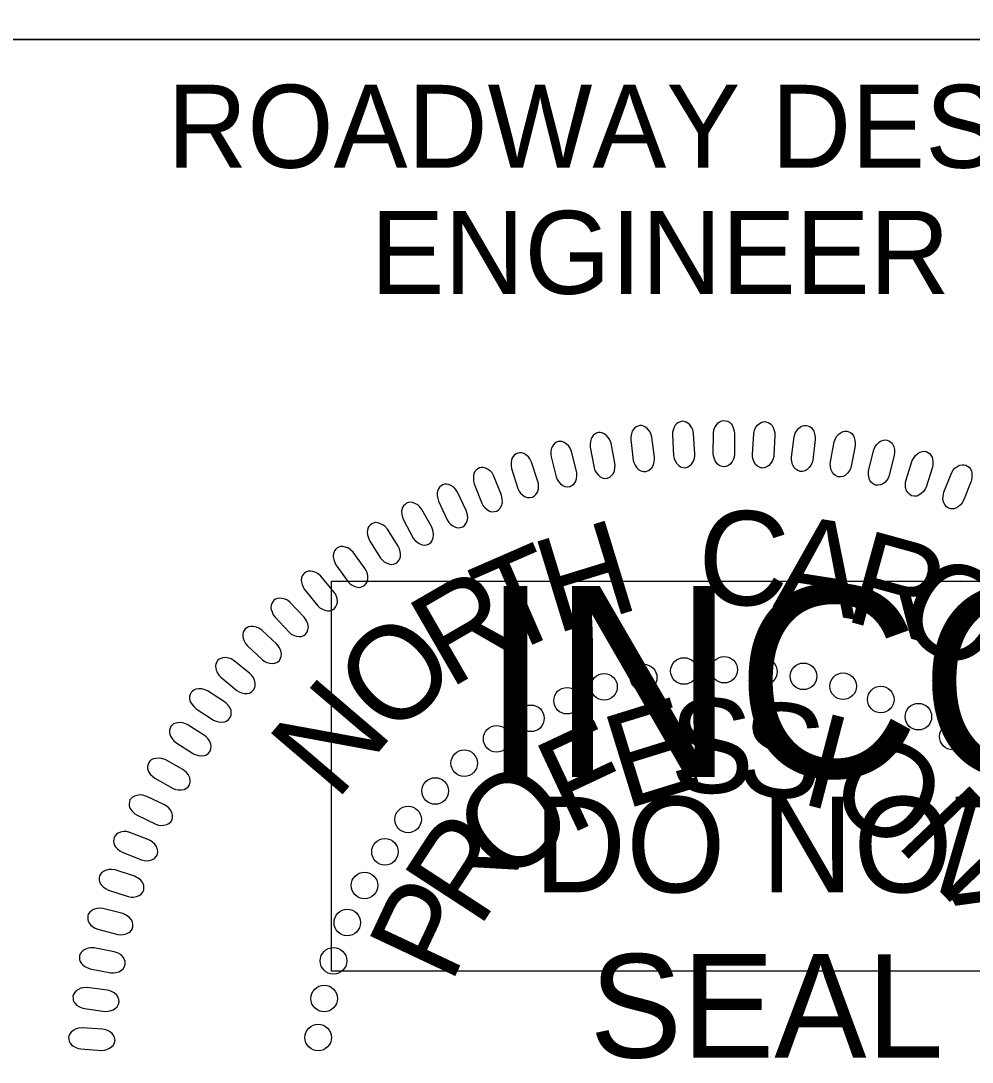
# Model space of a CAD drawing. Extents: x 497599 to 513368, y 404140 to 482942.
# Drawn here: x 507166.5 to 507223.8, y 439749.5 to 439812.2 of the extents above; entities that cross this region are included whole.
import ezdxf

# ---------------------------------------------------------------- set-up
doc = ezdxf.new("R2010")
doc.units = 0
for name, color, linetype in [('Sheet PE Seal Cell', 7, 'Continuous'), ('Sheet Profile CELL', 7, 'Continuous'), ('Sheet Sticker Incomplete CELL', 7, 'Continuous')]:
    doc.layers.add(name, color=color, linetype=linetype)

msp = doc.modelspace()

# ---------------------------------------------------------------- linework, layer by layer
at = {"layer": 'Sheet PE Seal Cell'}
for points in [[(507204.659, 439785.912), (507204.505, 439787.129), (507204.441, 439787.343), (507204.372, 439787.474), (507204.239, 439787.629), (507204.129, 439787.725), (507204.008, 439787.79), (507203.899, 439787.817), (507203.785, 439787.823), (507203.676, 439787.789), (507203.562, 439787.744), (507203.465, 439787.672), (507203.374, 439787.56), (507203.325, 439787.473), (507203.276, 439787.316), (507203.239, 439787.131), (507203.237, 439786.97), (507203.387, 439785.722), (507203.43, 439785.557), (507203.492, 439785.424), (507203.601, 439785.277), (507203.73, 439785.152), (507203.836, 439785.085), (507203.999, 439785.045), (507204.15, 439785.044), (507204.294, 439785.102), (507204.391, 439785.165), (507204.505, 439785.28), (507204.602, 439785.463), (507204.646, 439785.649), (507204.66, 439785.782)], [(507207.097, 439786.115), (507207.02, 439787.339), (507206.969, 439787.556), (507206.909, 439787.692), (507206.786, 439787.855), (507206.682, 439787.958), (507206.565, 439788.03), (507206.459, 439788.064), (507206.345, 439788.076), (507206.235, 439788.049), (507206.117, 439788.012), (507206.016, 439787.946), (507205.918, 439787.84), (507205.864, 439787.757), (507205.805, 439787.603), (507205.757, 439787.42), (507205.745, 439787.26), (507205.816, 439786.005), (507205.849, 439785.837), (507205.902, 439785.701), (507206.001, 439785.547), (507206.123, 439785.415), (507206.224, 439785.341), (507206.385, 439785.291), (507206.535, 439785.28), (507206.682, 439785.33), (507206.783, 439785.386), (507206.904, 439785.494), (507207.013, 439785.67), (507207.068, 439785.854), (507207.091, 439785.985)], [(507208.212, 439786.124), (507208.213, 439787.351), (507208.25, 439787.57), (507208.303, 439787.71), (507208.415, 439787.879), (507208.512, 439787.989), (507208.624, 439788.069), (507208.729, 439788.109), (507208.841, 439788.129), (507208.953, 439788.108), (507209.073, 439788.079), (507209.177, 439788.019), (507209.282, 439787.919), (507209.342, 439787.839), (507209.409, 439787.689), (507209.469, 439787.51), (507209.491, 439787.35), (507209.498, 439786.094), (507209.476, 439785.924), (507209.431, 439785.785), (507209.341, 439785.625), (507209.229, 439785.485), (507209.132, 439785.406), (507208.974, 439785.346), (507208.825, 439785.326), (507208.676, 439785.366), (507208.571, 439785.416), (507208.444, 439785.515), (507208.324, 439785.685), (507208.257, 439785.865), (507208.227, 439785.995)], [(507210.572, 439786.097), (507210.649, 439787.322), (507210.7, 439787.539), (507210.761, 439787.674), (507210.884, 439787.837), (507210.987, 439787.94), (507211.105, 439788.013), (507211.212, 439788.045), (507211.325, 439788.058), (507211.435, 439788.031), (507211.553, 439787.994), (507211.654, 439787.928), (507211.752, 439787.822), (507211.806, 439787.738), (507211.864, 439787.585), (507211.912, 439787.402), (507211.925, 439787.242), (507211.853, 439785.986), (507211.82, 439785.819), (507211.766, 439785.682), (507211.666, 439785.529), (507211.546, 439785.397), (507211.444, 439785.323), (507211.283, 439785.273), (507211.133, 439785.262), (507210.986, 439785.312), (507210.885, 439785.369), (507210.764, 439785.476), (507210.656, 439785.652), (507210.6, 439785.836), (507210.578, 439785.968)], [(507212.934, 439785.923), (507213.088, 439787.139), (507213.153, 439787.353), (507213.222, 439787.484), (507213.355, 439787.638), (507213.465, 439787.735), (507213.587, 439787.8), (507213.695, 439787.827), (507213.809, 439787.832), (507213.918, 439787.798), (507214.032, 439787.754), (507214.129, 439787.681), (507214.22, 439787.569), (507214.269, 439787.482), (507214.318, 439787.325), (507214.354, 439787.14), (507214.356, 439786.979), (507214.206, 439785.731), (507214.162, 439785.566), (507214.1, 439785.433), (507213.991, 439785.286), (507213.862, 439785.162), (507213.756, 439785.095), (507213.593, 439785.055), (507213.442, 439785.054), (507213.298, 439785.112), (507213.201, 439785.175), (507213.087, 439785.29), (507212.99, 439785.473), (507212.946, 439785.66), (507212.933, 439785.792)], [(507202.278, 439785.545), (507202.048, 439786.749), (507201.97, 439786.958), (507201.893, 439787.085), (507201.751, 439787.231), (507201.635, 439787.32), (507201.51, 439787.378), (507201.4, 439787.397), (507201.286, 439787.396), (507201.179, 439787.356), (507201.068, 439787.304), (507200.976, 439787.226), (507200.891, 439787.108), (507200.848, 439787.018), (507200.81, 439786.858), (507200.785, 439786.671), (507200.792, 439786.51), (507201.02, 439785.275), (507201.074, 439785.112), (507201.144, 439784.983), (507201.262, 439784.843), (507201.399, 439784.727), (507201.509, 439784.667), (507201.674, 439784.638), (507201.825, 439784.646), (507201.964, 439784.713), (507202.058, 439784.782), (507202.164, 439784.903), (507202.25, 439785.092), (507202.282, 439785.281), (507202.287, 439785.414)], [(507215.273, 439785.636), (507215.504, 439786.841), (507215.582, 439787.049), (507215.659, 439787.176), (507215.801, 439787.322), (507215.917, 439787.411), (507216.042, 439787.469), (507216.152, 439787.488), (507216.267, 439787.487), (507216.373, 439787.446), (507216.485, 439787.394), (507216.576, 439787.316), (507216.66, 439787.198), (507216.704, 439787.109), (507216.742, 439786.949), (507216.767, 439786.762), (507216.759, 439786.6), (507216.531, 439785.365), (507216.476, 439785.203), (507216.406, 439785.074), (507216.288, 439784.934), (507216.152, 439784.818), (507216.042, 439784.758), (507215.876, 439784.729), (507215.726, 439784.737), (507215.586, 439784.804), (507215.493, 439784.873), (507215.387, 439784.995), (507215.301, 439785.184), (507215.269, 439785.373), (507215.264, 439785.506)], [(507217.579, 439785.162), (507217.884, 439786.35), (507217.975, 439786.553), (507218.06, 439786.676), (507218.211, 439786.812), (507218.332, 439786.894), (507218.461, 439786.943), (507218.572, 439786.956), (507218.686, 439786.948), (507218.789, 439786.9), (507218.898, 439786.841), (507218.984, 439786.758), (507219.06, 439786.635), (507219.099, 439786.543), (507219.127, 439786.381), (507219.14, 439786.192), (507219.123, 439786.032), (507218.816, 439784.813), (507218.752, 439784.655), (507218.674, 439784.531), (507218.547, 439784.398), (507218.404, 439784.291), (507218.29, 439784.238), (507218.123, 439784.219), (507217.974, 439784.237), (507217.839, 439784.313), (507217.75, 439784.387), (507217.652, 439784.515), (507217.578, 439784.709), (507217.558, 439784.9), (507217.561, 439785.033)], [(507199.972, 439785.072), (507199.668, 439786.26), (507199.577, 439786.463), (507199.492, 439786.586), (507199.341, 439786.722), (507199.219, 439786.804), (507199.091, 439786.854), (507198.979, 439786.867), (507198.866, 439786.858), (507198.762, 439786.811), (507198.654, 439786.752), (507198.568, 439786.668), (507198.491, 439786.546), (507198.453, 439786.454), (507198.425, 439786.292), (507198.412, 439786.103), (507198.429, 439785.943), (507198.734, 439784.724), (507198.798, 439784.565), (507198.876, 439784.441), (507199.003, 439784.309), (507199.146, 439784.201), (507199.26, 439784.149), (507199.427, 439784.129), (507199.577, 439784.147), (507199.712, 439784.223), (507199.801, 439784.297), (507199.899, 439784.426), (507199.972, 439784.619), (507199.993, 439784.81), (507199.99, 439784.943)], [(507219.828, 439784.54), (507220.208, 439785.707), (507220.312, 439785.904), (507220.404, 439786.02), (507220.564, 439786.147), (507220.69, 439786.221), (507220.821, 439786.263), (507220.933, 439786.268), (507221.046, 439786.252), (507221.146, 439786.199), (507221.251, 439786.133), (507221.332, 439786.044), (507221.4, 439785.917), (507221.432, 439785.822), (507221.45, 439785.659), (507221.452, 439785.47), (507221.424, 439785.311), (507221.042, 439784.114), (507220.969, 439783.959), (507220.882, 439783.841), (507220.748, 439783.716), (507220.598, 439783.619), (507220.481, 439783.573), (507220.313, 439783.564), (507220.164, 439783.592), (507220.035, 439783.676), (507219.951, 439783.756), (507219.861, 439783.89), (507219.8, 439784.088), (507219.791, 439784.28), (507219.803, 439784.412)], [(507197.639, 439784.452), (507197.26, 439785.618), (507197.157, 439785.815), (507197.064, 439785.932), (507196.905, 439786.059), (507196.779, 439786.133), (507196.648, 439786.174), (507196.535, 439786.18), (507196.423, 439786.165), (507196.322, 439786.111), (507196.218, 439786.046), (507196.137, 439785.957), (507196.068, 439785.829), (507196.036, 439785.735), (507196.018, 439785.572), (507196.016, 439785.383), (507196.044, 439785.223), (507196.425, 439784.026), (507196.499, 439783.872), (507196.585, 439783.753), (507196.719, 439783.629), (507196.869, 439783.531), (507196.986, 439783.485), (507197.154, 439783.476), (507197.302, 439783.504), (507197.432, 439783.588), (507197.516, 439783.668), (507197.606, 439783.801), (507197.668, 439784), (507197.676, 439784.191), (507197.665, 439784.324)], [(507195.438, 439783.635), (507194.987, 439784.776), (507194.871, 439784.966), (507194.772, 439785.077), (507194.605, 439785.193), (507194.474, 439785.26), (507194.34, 439785.292), (507194.228, 439785.291), (507194.117, 439785.268), (507194.02, 439785.208), (507193.919, 439785.137), (507193.844, 439785.043), (507193.783, 439784.911), (507193.758, 439784.815), (507193.75, 439784.651), (507193.76, 439784.462), (507193.798, 439784.306), (507194.253, 439783.134), (507194.336, 439782.985), (507194.43, 439782.872), (507194.572, 439782.756), (507194.727, 439782.668), (507194.847, 439782.629), (507195.015, 439782.631), (507195.162, 439782.668), (507195.285, 439782.76), (507195.364, 439782.845), (507195.446, 439782.984), (507195.496, 439783.186), (507195.491, 439783.378), (507195.472, 439783.509)], [(507222.112, 439783.805), (507222.564, 439784.945), (507222.68, 439785.136), (507222.779, 439785.247), (507222.946, 439785.363), (507223.077, 439785.429), (507223.211, 439785.462), (507223.323, 439785.46), (507223.434, 439785.438), (507223.531, 439785.378), (507223.631, 439785.306), (507223.706, 439785.211), (507223.767, 439785.08), (507223.793, 439784.984), (507223.801, 439784.82), (507223.791, 439784.631), (507223.752, 439784.475), (507223.296, 439783.304), (507223.212, 439783.155), (507223.12, 439783.041), (507222.978, 439782.926), (507222.822, 439782.837), (507222.702, 439782.799), (507222.534, 439782.802), (507222.388, 439782.838), (507222.264, 439782.93), (507222.184, 439783.015), (507222.103, 439783.154), (507222.055, 439783.356), (507222.058, 439783.548), (507222.078, 439783.679)], [(507193.32, 439782.702), (507192.799, 439783.813), (507192.671, 439783.995), (507192.564, 439784.099), (507192.391, 439784.206), (507192.256, 439784.263), (507192.121, 439784.287), (507192.009, 439784.279), (507191.899, 439784.249), (507191.806, 439784.184), (507191.711, 439784.106), (507191.642, 439784.007), (507191.589, 439783.872), (507191.569, 439783.775), (507191.572, 439783.611), (507191.594, 439783.422), (507191.642, 439783.269), (507192.17, 439782.129), (507192.262, 439781.984), (507192.362, 439781.877), (507192.511, 439781.771), (507192.672, 439781.692), (507192.794, 439781.662), (507192.962, 439781.674), (507193.105, 439781.72), (507193.224, 439781.82), (507193.297, 439781.909), (507193.37, 439782.053), (507193.406, 439782.257), (507193.39, 439782.449), (507193.362, 439782.579)], [(507191.237, 439781.688), (507190.646, 439782.764), (507190.508, 439782.938), (507190.396, 439783.035), (507190.216, 439783.13), (507190.078, 439783.179), (507189.941, 439783.195), (507189.83, 439783.18), (507189.722, 439783.143), (507189.634, 439783.072), (507189.543, 439782.988), (507189.48, 439782.885), (507189.436, 439782.747), (507189.422, 439782.649), (507189.435, 439782.485), (507189.469, 439782.299), (507189.526, 439782.148), (507190.125, 439781.043), (507190.226, 439780.906), (507190.333, 439780.805), (507190.488, 439780.708), (507190.654, 439780.64), (507190.777, 439780.617), (507190.944, 439780.639), (507191.084, 439780.694), (507191.196, 439780.801), (507191.264, 439780.895), (507191.327, 439781.044), (507191.35, 439781.25), (507191.323, 439781.44), (507191.287, 439781.568)], [(507189.22, 439780.546), (507188.563, 439781.582), (507188.414, 439781.748), (507188.295, 439781.837), (507188.11, 439781.921), (507187.969, 439781.961), (507187.832, 439781.969), (507187.722, 439781.946), (507187.616, 439781.903), (507187.532, 439781.826), (507187.447, 439781.737), (507187.391, 439781.631), (507187.356, 439781.49), (507187.348, 439781.391), (507187.371, 439781.228), (507187.418, 439781.045), (507187.483, 439780.897), (507188.15, 439779.832), (507188.26, 439779.701), (507188.373, 439779.607), (507188.534, 439779.521), (507188.703, 439779.463), (507188.828, 439779.447), (507188.993, 439779.481), (507189.13, 439779.544), (507189.235, 439779.658), (507189.296, 439779.757), (507189.351, 439779.908), (507189.36, 439780.116), (507189.321, 439780.304), (507189.277, 439780.429)], [(507187.22, 439779.192), (507186.498, 439780.184), (507186.339, 439780.34), (507186.215, 439780.423), (507186.025, 439780.494), (507185.882, 439780.525), (507185.744, 439780.524), (507185.636, 439780.495), (507185.534, 439780.445), (507185.455, 439780.363), (507185.375, 439780.269), (507185.326, 439780.159), (507185.3, 439780.016), (507185.298, 439779.917), (507185.332, 439779.756), (507185.388, 439779.576), (507185.464, 439779.434), (507186.196, 439778.412), (507186.315, 439778.288), (507186.433, 439778.201), (507186.599, 439778.125), (507186.771, 439778.078), (507186.897, 439778.07), (507187.059, 439778.114), (507187.192, 439778.186), (507187.29, 439778.306), (507187.345, 439778.408), (507187.389, 439778.563), (507187.386, 439778.771), (507187.335, 439778.956), (507187.283, 439779.078)], [(507185.339, 439777.803), (507184.557, 439778.748), (507184.389, 439778.893), (507184.259, 439778.968), (507184.065, 439779.027), (507183.921, 439779.05), (507183.783, 439779.04), (507183.677, 439779.003), (507183.578, 439778.947), (507183.504, 439778.86), (507183.431, 439778.761), (507183.388, 439778.649), (507183.371, 439778.505), (507183.376, 439778.406), (507183.42, 439778.247), (507183.487, 439778.071), (507183.572, 439777.933), (507184.367, 439776.96), (507184.492, 439776.844), (507184.616, 439776.765), (507184.786, 439776.699), (507184.962, 439776.663), (507185.088, 439776.663), (507185.247, 439776.717), (507185.375, 439776.798), (507185.464, 439776.924), (507185.513, 439777.028), (507185.548, 439777.186), (507185.532, 439777.393), (507185.469, 439777.574), (507185.41, 439777.693)], [(507183.551, 439776.264), (507182.712, 439777.158), (507182.535, 439777.293), (507182.4, 439777.359), (507182.203, 439777.406), (507182.057, 439777.419), (507181.921, 439777.401), (507181.817, 439777.358), (507181.722, 439777.296), (507181.654, 439777.205), (507181.587, 439777.101), (507181.551, 439776.986), (507181.543, 439776.841), (507181.554, 439776.742), (507181.608, 439776.587), (507181.687, 439776.416), (507181.779, 439776.284), (507182.634, 439775.362), (507182.766, 439775.254), (507182.895, 439775.183), (507183.069, 439775.128), (507183.247, 439775.103), (507183.372, 439775.111), (507183.528, 439775.175), (507183.65, 439775.263), (507183.732, 439775.394), (507183.774, 439775.502), (507183.799, 439775.662), (507183.77, 439775.867), (507183.696, 439776.044), (507183.629, 439776.159)], [(507181.889, 439774.655), (507180.995, 439775.494), (507180.809, 439775.617), (507180.672, 439775.675), (507180.471, 439775.71), (507180.325, 439775.714), (507180.19, 439775.687), (507180.09, 439775.638), (507179.998, 439775.57), (507179.936, 439775.475), (507179.876, 439775.367), (507179.848, 439775.25), (507179.848, 439775.105), (507179.866, 439775.007), (507179.928, 439774.855), (507180.019, 439774.689), (507180.119, 439774.563), (507181.03, 439773.697), (507181.169, 439773.597), (507181.301, 439773.534), (507181.479, 439773.491), (507181.658, 439773.477), (507181.782, 439773.492), (507181.934, 439773.566), (507182.05, 439773.661), (507182.123, 439773.798), (507182.159, 439773.908), (507182.174, 439774.069), (507182.132, 439774.273), (507182.047, 439774.444), (507181.973, 439774.554)], [(507180.275, 439772.868), (507179.331, 439773.65), (507179.138, 439773.761), (507178.997, 439773.81), (507178.795, 439773.832), (507178.648, 439773.827), (507178.516, 439773.791), (507178.418, 439773.736), (507178.331, 439773.662), (507178.275, 439773.563), (507178.222, 439773.452), (507178.201, 439773.333), (507178.211, 439773.189), (507178.234, 439773.092), (507178.307, 439772.945), (507178.407, 439772.784), (507178.515, 439772.665), (507179.479, 439771.858), (507179.624, 439771.767), (507179.76, 439771.713), (507179.94, 439771.68), (507180.119, 439771.678), (507180.242, 439771.702), (507180.389, 439771.785), (507180.499, 439771.887), (507180.564, 439772.027), (507180.592, 439772.14), (507180.597, 439772.301), (507180.542, 439772.501), (507180.447, 439772.668), (507180.366, 439772.773)], [(507178.751, 439771.165), (507177.721, 439771.831), (507177.516, 439771.919), (507177.371, 439771.951), (507177.167, 439771.949), (507177.022, 439771.927), (507176.895, 439771.876), (507176.805, 439771.809), (507176.727, 439771.726), (507176.682, 439771.621), (507176.643, 439771.504), (507176.636, 439771.384), (507176.663, 439771.242), (507176.698, 439771.148), (507176.787, 439771.011), (507176.905, 439770.863), (507177.027, 439770.757), (507178.078, 439770.069), (507178.233, 439769.996), (507178.374, 439769.958), (507178.557, 439769.947), (507178.735, 439769.965), (507178.855, 439770.004), (507178.991, 439770.103), (507179.088, 439770.217), (507179.136, 439770.365), (507179.151, 439770.48), (507179.136, 439770.641), (507179.059, 439770.833), (507178.945, 439770.987), (507178.852, 439771.082)], [(507177.537, 439769.143), (507176.501, 439769.8), (507176.296, 439769.886), (507176.15, 439769.917), (507175.946, 439769.914), (507175.802, 439769.89), (507175.675, 439769.839), (507175.585, 439769.771), (507175.508, 439769.687), (507175.465, 439769.582), (507175.426, 439769.465), (507175.42, 439769.344), (507175.448, 439769.203), (507175.483, 439769.109), (507175.574, 439768.972), (507175.693, 439768.826), (507175.816, 439768.721), (507176.873, 439768.041), (507177.028, 439767.969), (507177.17, 439767.932), (507177.352, 439767.923), (507177.53, 439767.942), (507177.65, 439767.981), (507177.785, 439768.082), (507177.881, 439768.198), (507177.928, 439768.345), (507177.942, 439768.46), (507177.926, 439768.621), (507177.847, 439768.812), (507177.732, 439768.966), (507177.638, 439769.061)], [(507176.233, 439767.093), (507175.158, 439767.685), (507174.948, 439767.758), (507174.8, 439767.78), (507174.598, 439767.763), (507174.455, 439767.73), (507174.331, 439767.671), (507174.246, 439767.598), (507174.174, 439767.51), (507174.138, 439767.402), (507174.106, 439767.283), (507174.108, 439767.162), (507174.145, 439767.023), (507174.186, 439766.932), (507174.285, 439766.8), (507174.413, 439766.662), (507174.542, 439766.565), (507175.639, 439765.953), (507175.799, 439765.89), (507175.943, 439765.863), (507176.126, 439765.864), (507176.302, 439765.895), (507176.419, 439765.942), (507176.547, 439766.051), (507176.636, 439766.172), (507176.673, 439766.322), (507176.681, 439766.437), (507176.654, 439766.598), (507176.563, 439766.783), (507176.439, 439766.929), (507176.339, 439767.018)], [(507175.124, 439764.969), (507174.014, 439765.492), (507173.8, 439765.552), (507173.651, 439765.565), (507173.45, 439765.535), (507173.309, 439765.494), (507173.19, 439765.426), (507173.109, 439765.349), (507173.043, 439765.256), (507173.013, 439765.146), (507172.99, 439765.024), (507172.999, 439764.905), (507173.045, 439764.768), (507173.092, 439764.68), (507173.198, 439764.555), (507173.335, 439764.424), (507173.47, 439764.335), (507174.604, 439763.793), (507174.767, 439763.742), (507174.912, 439763.723), (507175.094, 439763.736), (507175.269, 439763.778), (507175.382, 439763.832), (507175.504, 439763.948), (507175.585, 439764.075), (507175.612, 439764.227), (507175.612, 439764.344), (507175.576, 439764.501), (507175.474, 439764.681), (507175.34, 439764.818), (507175.235, 439764.901)], [(507174.185, 439762.851), (507173.045, 439763.303), (507172.827, 439763.348), (507172.678, 439763.352), (507172.479, 439763.31), (507172.341, 439763.26), (507172.226, 439763.185), (507172.15, 439763.102), (507172.09, 439763.005), (507172.068, 439762.894), (507172.051, 439762.771), (507172.068, 439762.653), (507172.122, 439762.519), (507172.174, 439762.433), (507172.289, 439762.316), (507172.434, 439762.194), (507172.574, 439762.114), (507173.739, 439761.644), (507173.905, 439761.603), (507174.051, 439761.593), (507174.232, 439761.618), (507174.404, 439761.671), (507174.514, 439761.732), (507174.628, 439761.855), (507174.701, 439761.987), (507174.719, 439762.14), (507174.711, 439762.256), (507174.665, 439762.411), (507174.552, 439762.584), (507174.409, 439762.713), (507174.299, 439762.789)], [(507173.309, 439760.662), (507172.143, 439761.041), (507171.922, 439761.073), (507171.773, 439761.067), (507171.577, 439761.013), (507171.443, 439760.954), (507171.332, 439760.872), (507171.263, 439760.785), (507171.209, 439760.684), (507171.193, 439760.572), (507171.184, 439760.449), (507171.209, 439760.331), (507171.271, 439760.2), (507171.329, 439760.119), (507171.45, 439760.008), (507171.602, 439759.896), (507171.747, 439759.825), (507172.94, 439759.429), (507173.108, 439759.399), (507173.255, 439759.398), (507173.434, 439759.434), (507173.601, 439759.498), (507173.708, 439759.565), (507173.813, 439759.695), (507173.878, 439759.832), (507173.886, 439759.987), (507173.871, 439760.101), (507173.816, 439760.253), (507173.692, 439760.419), (507173.542, 439760.539), (507173.428, 439760.607)], [(507172.605, 439758.406), (507171.416, 439758.711), (507171.195, 439758.73), (507171.046, 439758.714), (507170.854, 439758.648), (507170.724, 439758.581), (507170.618, 439758.492), (507170.554, 439758.401), (507170.507, 439758.297), (507170.498, 439758.184), (507170.497, 439758.06), (507170.529, 439757.944), (507170.6, 439757.818), (507170.662, 439757.74), (507170.791, 439757.637), (507170.949, 439757.535), (507171.098, 439757.473), (507172.313, 439757.153), (507172.483, 439757.133), (507172.63, 439757.141), (507172.806, 439757.189), (507172.969, 439757.262), (507173.071, 439757.337), (507173.168, 439757.474), (507173.225, 439757.614), (507173.223, 439757.768), (507173.201, 439757.882), (507173.136, 439758.03), (507173.002, 439758.188), (507172.845, 439758.298), (507172.726, 439758.359)], [(507172.094, 439756.11), (507170.889, 439756.34), (507170.666, 439756.345), (507170.519, 439756.32), (507170.331, 439756.242), (507170.205, 439756.167), (507170.106, 439756.071), (507170.047, 439755.976), (507170.006, 439755.87), (507170.006, 439755.756), (507170.012, 439755.633), (507170.051, 439755.519), (507170.13, 439755.398), (507170.197, 439755.324), (507170.331, 439755.229), (507170.496, 439755.137), (507170.648, 439755.085), (507171.882, 439754.841), (507172.053, 439754.832), (507172.198, 439754.85), (507172.371, 439754.908), (507172.53, 439754.992), (507172.626, 439755.073), (507172.714, 439755.215), (507172.762, 439755.359), (507172.751, 439755.513), (507172.721, 439755.625), (507172.648, 439755.769), (507172.504, 439755.918), (507172.34, 439756.018), (507172.218, 439756.072)], [(507171.673, 439753.796), (507170.456, 439753.95), (507170.234, 439753.941), (507170.088, 439753.907), (507169.906, 439753.816), (507169.785, 439753.734), (507169.692, 439753.633), (507169.639, 439753.534), (507169.605, 439753.425), (507169.611, 439753.311), (507169.626, 439753.189), (507169.672, 439753.078), (507169.758, 439752.961), (507169.83, 439752.892), (507169.97, 439752.806), (507170.14, 439752.725), (507170.296, 439752.682), (507171.541, 439752.517), (507171.713, 439752.518), (507171.856, 439752.545), (507172.026, 439752.613), (507172.178, 439752.708), (507172.27, 439752.794), (507172.349, 439752.942), (507172.388, 439753.088), (507172.367, 439753.241), (507172.33, 439753.351), (507172.248, 439753.49), (507172.094, 439753.63), (507171.924, 439753.719), (507171.8, 439753.765)], [(507171.387, 439751.452), (507170.163, 439751.529), (507169.941, 439751.506), (507169.798, 439751.463), (507169.622, 439751.362), (507169.506, 439751.271), (507169.42, 439751.165), (507169.373, 439751.063), (507169.346, 439750.952), (507169.36, 439750.839), (507169.382, 439750.717), (507169.434, 439750.609), (507169.527, 439750.499), (507169.603, 439750.434), (507169.748, 439750.357), (507169.924, 439750.286), (507170.082, 439750.254), (507171.335, 439750.167), (507171.506, 439750.178), (507171.648, 439750.215), (507171.813, 439750.294), (507171.959, 439750.397), (507172.045, 439750.489), (507172.115, 439750.642), (507172.144, 439750.79), (507172.114, 439750.941), (507172.07, 439751.05), (507171.979, 439751.183), (507171.817, 439751.312), (507171.642, 439751.391), (507171.515, 439751.429)]]:
    msp.add_lwpolyline(points, close=True, dxfattribs=at)
for centre in [(507206.441, 439773.028), (507208.869, 439773.107), (507211.258, 439772.987), (507204.012, 439772.631), (507213.647, 439772.707), (507201.623, 439772.074), (507216.035, 439772.109), (507199.393, 439771.238), (507218.304, 439771.311), (507197.219, 439770.177), (507220.573, 439770.275), (507195.148, 439768.943), (507222.643, 439769.079), (507193.197, 439767.47), (507191.444, 439765.797), (507189.811, 439764.084), (507188.417, 439762.133), (507187.182, 439760.102), (507186.146, 439757.871), (507185.31, 439755.561), (507184.752, 439753.29), (507184.392, 439750.94)]:
    msp.add_circle(centre, 0.801, dxfattribs=at)
at = {"layer": 'Sheet Profile CELL'}
for points in [[(507158.628, 439836.144), (507358.678, 439836.144), (507358.678, 439811.094), (507158.628, 439811.094)], [(507158.628, 439811.094), (507258.678, 439811.094), (507258.678, 439698.594), (507158.628, 439698.594)]]:
    msp.add_lwpolyline(points, close=True, dxfattribs=at)
at = {"layer": 'Sheet Sticker Incomplete CELL'}
msp.add_lwpolyline([(507185.195, 439754.938), (507185.195, 439778.438), (507332.195, 439778.438), (507332.195, 439754.938)], close=True, dxfattribs=at)

# ---------------------------------------------------------------- texts
at = {"layer": 'Sheet PE Seal Cell'}
for s, height, rotation, p in [('C', 5.669, 357.58768, (507207.187, 439777.119)), ('H', 5.669, 17.05575, (507198.682, 439775.235)), ('A', 5.669, 351.09832, (507211.763, 439776.91)), ('R', 5.669, 344.60896, (507215.969, 439776.116)), ('T', 5.669, 23.5451, (507195.503, 439773.825)), ('O', 5.669, 331.63025, (507218.924, 439775.462)), ('R', 5.669, 30.03446, (507192.282, 439771.907)), ('O', 5.669, 43.01317, (507188.807, 439768.878)), ('N', 5.669, 49.50253, (507185.46, 439765.123)), ('E', 5.669, 17.16862, (507202.878, 439764.666)), ('S', 5.669, 1.28903, (507205.646, 439765.626)), ('S', 5.669, 353.34923, (507209.506, 439765.727)), ('F', 5.669, 25.10842, (507199.488, 439763.128)), ('I', 5.669, 345.40944, (507213.307, 439765.095)), ('O', 5.669, 329.52984, (507214.81, 439764.924)), ('O', 5.669, 40.98802, (507195.791, 439759.989)), ('N', 5.669, 313.65025, (507219.122, 439762.619)), ('R', 5.669, 56.86761, (507194.077, 439757.443)), ('P', 5.669, 64.80741, (507192.391, 439754.081)), ('A', 5.669, 297.77065, (507222.459, 439759.539)), ('SEAL', 6.2363, 359.98136, (507200.762, 439749.732))]:
    msp.add_text(s, height=height, rotation=rotation, dxfattribs=at).set_placement(p)
at = {"layer": 'Sheet Profile CELL'}
for s, p in [('ROADWAY DESIGN', (507175.29, 439803.357)), ('ENGINEER', (507187.54, 439795.757))]:
    msp.add_text(s, height=5.0001, dxfattribs=at).set_placement(p)
at = {"layer": 'Sheet Sticker Incomplete CELL'}
for s, height, p in [('INCOMPLETE PLANS', 11.52, (507194.145, 439766.638)), ('DO NOT USE FOR R/W ACQUISITION', 5.76, (507197.395, 439759.688))]:
    msp.add_text(s, height=height, dxfattribs=at).set_placement(p)

doc.saveas('drawing.dxf')
